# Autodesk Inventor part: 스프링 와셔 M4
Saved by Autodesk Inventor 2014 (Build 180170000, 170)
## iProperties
Created: 2026-04
Part Number: 스프링 와셔 M4
Material: 일반
Document SubType Name: Modeling
Designer: dg
Density: 1 g/cm^3
Appearance: 기본값
Author: dg
Author: jhkim
Description: 스프링 잠금 와셔
Creation Date: 2026-03-26
Sending System: Autodesk Inventor 2026
Preprocessor: ST-DEVELOPER v20.1
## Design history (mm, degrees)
node "스프링 와셔 M41"
body "Solid1"
node "기준1"
